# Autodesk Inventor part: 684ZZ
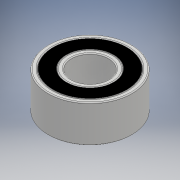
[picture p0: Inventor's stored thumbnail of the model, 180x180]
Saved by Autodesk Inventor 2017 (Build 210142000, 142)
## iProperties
Created: 2021-01
Part Number: 684ZZ
Material: Generic
Document SubType Name: Modeling
Designer: WindowsX
Density: 1 g/cm^3
Appearance: Default
Author: WindowsX
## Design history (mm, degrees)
sketch "Szkic1"
  geometry: C1 r 4.5 at (0, 0); C2 r 4 at (0, 0); 1 further point
  constraints: 2 centre point, 2 coincident
  dimensions: "d0" = 9 diameter of C1; "d1" = 8 diameter of C2
extrude "Wyciągnięcie proste1" new body sketch "Szkic1" distance "d2" = 4; taper "d3" = 0 deg
fillet "Zaokrąglenie1" dims "d4" = 0.1
sketch "Szkic2"
  geometry: C1 r 2 at (0, 0); C2 r 2.5 at (0, 0); 1 further point
  constraints: 2 centre point, 2 coincident
  dimensions: "d5" = 4 diameter of C1; "d6" = 5 diameter of C2
extrude "Wyciągnięcie proste2" join sketch "Szkic2" distance "d7" = 4; taper "d8" = 0 deg
fillet "Zaokrąglenie2" dims "d9" = 0.1
sketch "Szkic3"
  geometry: C1 r 3.95 at (0, 0); C2 r 2.55 at (0, 0); 1 further point
  constraints: 2 centre point, 2 coincident
  dimensions: "d10" = 7.9 diameter of C1; "d11" = 5.1 diameter of C2
extrude "Wyciągnięcie proste3" join sketch "Szkic3" distance "d12" = 4; taper "d13" = 0 deg
node "Bryła1"
